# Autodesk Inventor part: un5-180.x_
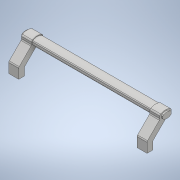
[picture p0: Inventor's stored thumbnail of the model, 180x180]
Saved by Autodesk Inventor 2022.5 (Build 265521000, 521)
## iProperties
Part Number: un5-180.x_
Material: 一般
Document SubType Name: Modeling
Designer: ImaoCorp
Density: 1 g/cm^3
Appearance: 既定
Sending System: SOLIDWORKS 2017-2017317
MC: AMD64
MC_MODEL: Intel64 Family 6 Model 60 Stepping 3, GenuineIntel
OS: Windows_NT
FRU: Parasolid Version 29.0, build 201,  4-17-2017
FORMAT: text
GUISE: transmit
KEY: un5-180
FILE: un5-180.x_t
DATE: Thu Sep 19 11:10:18 2019
Author: ImaoCorp
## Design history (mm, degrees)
feature "Base1"
node "ソリッド1"
